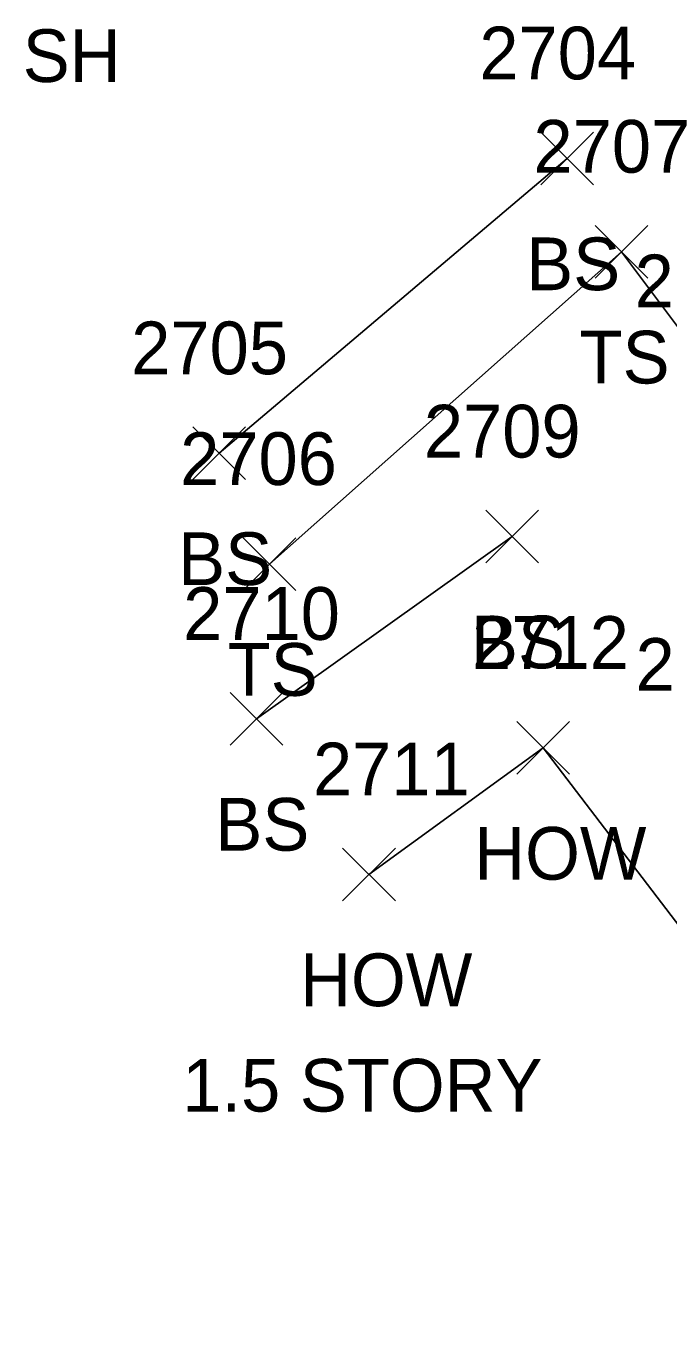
# Model space of a CAD drawing. Extents: x 1634209 to 1639641, y 608564 to 612258.
# Drawn here: x 1639240.24 to 1639264.61, y 611021.24 to 611070.39 of the extents above; entities that cross this region are included whole.
import ezdxf

# ---------------------------------------------------------------- set-up
doc = ezdxf.new("R2010")
doc.units = 0
for name, color, linetype in [('L_A', 7, 'Continuous'), ('L_C', 7, 'Continuous'), ('L_I', 7, 'Continuous'), ('L_TIC', 7, 'Continuous'), ('LBC', 7, 'Continuous'), ('LELB', 7, 'Continuous')]:
    doc.layers.add(name, color=color, linetype=linetype)

msp = doc.modelspace()

# ---------------------------------------------------------------- linework, layer by layer
at = {"layer": 'L_TIC'}
for points in [[(1639259.783, 611064.358), (1639261.783, 611066.358)], [(1639261.783, 611064.358), (1639259.783, 611066.358)], [(1639261.839, 611060.818), (1639263.839, 611062.818)], [(1639263.839, 611060.818), (1639261.839, 611062.818)], [(1639246.572, 611053.168), (1639248.572, 611055.168)], [(1639248.572, 611053.168), (1639246.572, 611055.168)], [(1639257.687, 611050.008), (1639259.687, 611052.008)], [(1639259.687, 611050.008), (1639257.687, 611052.008)], [(1639248.482, 611048.965), (1639250.482, 611050.965)], [(1639250.482, 611048.965), (1639248.482, 611050.965)], [(1639247.984, 611043.089), (1639249.984, 611045.089)], [(1639249.984, 611043.089), (1639247.984, 611045.089)], [(1639258.865, 611041.988), (1639260.865, 611043.988)], [(1639260.865, 611041.988), (1639258.865, 611043.988)], [(1639252.257, 611037.187), (1639254.257, 611039.187)], [(1639254.257, 611037.187), (1639252.257, 611039.187)]]:
    msp.add_lwpolyline(points, dxfattribs=at)
at = {"layer": 'LBC'}
msp.add_lwpolyline([(1639253.257, 611038.187), (1639259.865, 611042.988), (1639272.978, 611025.826), (1639267.592, 611021.235)], dxfattribs=at)
at = {"layer": 'LELB'}
for points in [[(1639260.783, 611065.358), (1639247.572, 611054.168)], [(1639249.482, 611049.965), (1639262.839, 611061.818), (1639266.678, 611056.709)], [(1639258.687, 611051.008), (1639248.984, 611044.089)]]:
    msp.add_lwpolyline(points, dxfattribs=at)

# ---------------------------------------------------------------- texts
at = {"layer": 'L_A'}
for s, p in [('SH', (1639240.114, 611068.259)), ('BS', (1639259.224, 611060.358)), ('TS', (1639261.248, 611056.818)), ('BS', (1639246.013, 611049.168)), ('BS', (1639257.128, 611046.008)), ('TS', (1639247.892, 611044.965)), ('BS', (1639247.425, 611039.089)), ('HOW', (1639257.251, 611037.988)), ('HOW', (1639250.642, 611033.187))]:
    msp.add_text(s, height=2, dxfattribs=at).set_placement(p)
at = {"layer": 'L_C'}
msp.add_text('1.5 STORY', height=2, dxfattribs=at).set_placement((1639246.17, 611029.187))
at = {"layer": 'L_I'}
for s, p in [('2704', (1639257.445, 611068.358)), ('2707', (1639259.5, 611064.818)), ('2708', (1639263.34, 611059.709)), ('2705', (1639244.233, 611057.168)), ('2709', (1639255.341, 611054.008)), ('2706', (1639246.089, 611052.965)), ('2710', (1639246.205, 611047.089)), ('2712', (1639257.173, 611045.988)), ('2713', (1639263.374, 611045.154)), ('2711', (1639251.131, 611041.187))]:
    msp.add_text(s, height=2, dxfattribs=at).set_placement(p)

doc.saveas('drawing.dxf')
